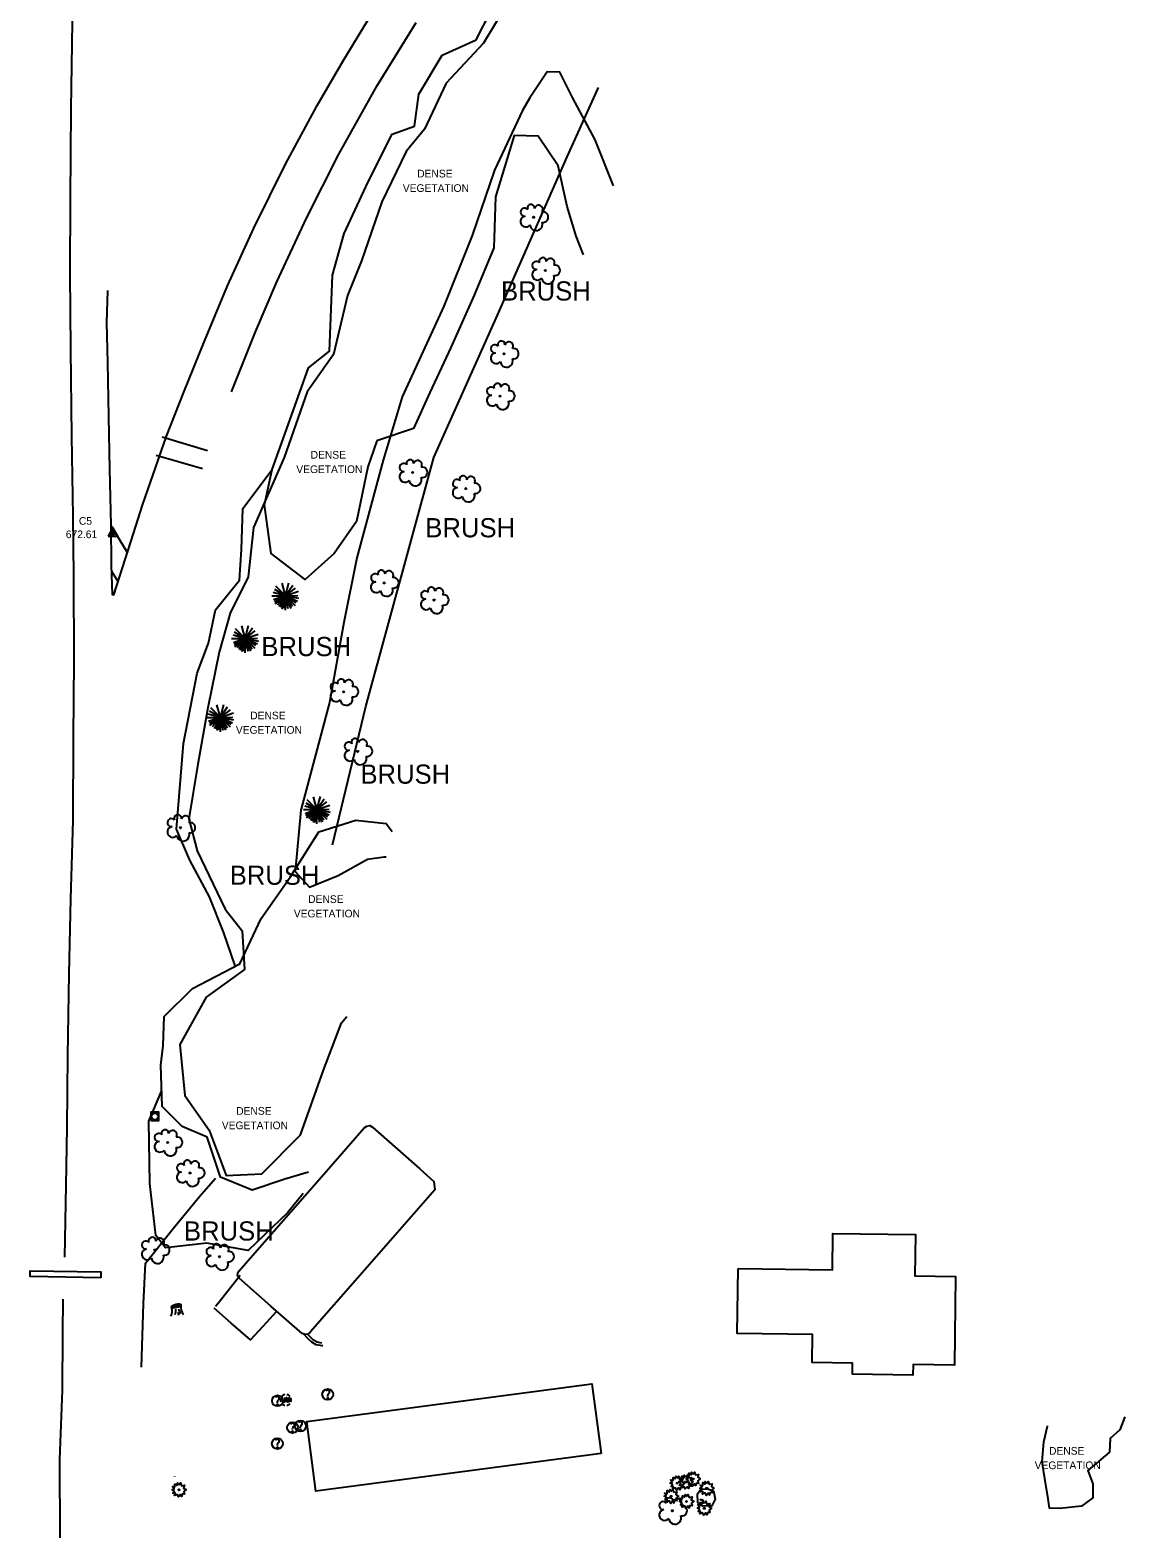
# Model space of a CAD drawing. Extents: x 2129547 to 2134906, y 657330 to 659734.
# Drawn here: x 2132485 to 2132885, y 657694 to 658244 of the extents above; entities that cross this region are included whole.
import ezdxf

# ---------------------------------------------------------------- set-up
doc = ezdxf.new("R2010")
doc.units = 0
for name, color, linetype in [('BD_X_Building', 7, 'Continuous'), ('PM_X_Crosswalk', 7, 'Continuous'), ('PM_X_Edge_Line', 7, 'Continuous'), ('PM_X_Lane_Line', 7, 'Continuous'), ('PM_X_Stop_Line', 7, 'Continuous'), ('PM_X_Transverse_Line', 7, 'Continuous'), ('PV_X_Parking_Lot', 7, 'Continuous'), ('RD_X_Cells', 7, 'Continuous'), ('RD_X_Concrete_Pad', 7, 'Continuous'), ('RD_X_Fence', 7, 'Continuous'), ('RD_X_GR_Rt', 7, 'Continuous'), ('RD_X_Misc_Items', 7, 'Continuous'), ('RD_X_Wall', 7, 'Continuous'), ('SG_X_Poles', 7, 'Continuous'), ('SV_P_Aerial_Targets', 7, 'Continuous'), ('UT_X_Misc_Cells', 7, 'Continuous'), ('UT_X_Unknown_Cells', 7, 'Continuous'), ('VG_X_Cells', 7, 'Continuous'), ('VG_X_Shrub_Line_Lt', 7, 'Continuous'), ('VG_X_Text', 7, 'Continuous'), ('VG_X_Tree_Line_Lt', 7, 'Continuous')]:
    doc.layers.add(name, color=color, linetype=linetype)

# ---------------------------------------------------------------- blocks, each defined once
blk = doc.blocks.new('DM')
at = {"layer": 'UT_X_Misc_Cells'}
blk.add_circle((0, 0), 0.00254, dxfattribs=at)
blk.add_arc((0.01016, 0), 0.01016, 90, 270, dxfattribs=at)
blk = doc.blocks.new('FCTRL')
at = {"layer": 'SV_P_Aerial_Targets'}
blk.add_lwpolyline([(-0.0229, -0.0147), (0.0229, -0.0147), (0, 0.0262)], close=True, dxfattribs=at)
for radius in [0.00889, 0.00203]:
    blk.add_circle((0, 0), radius, dxfattribs=at)
blk = doc.blocks.new('SHRUB')
at = {"layer": 'VG_X_Cells'}
blk.add_lwpolyline([(-0.0011, 0.023), (0.0066, 0.0323), (0.0119, 0.0189), (0.0257, 0.0212), (0.0214, 0.0084), (0.0334, 0.0008), (0.0226, -0.0085), (0.0257, -0.0201), (0.0162, -0.0192), (0.012, -0.0308), (0.0066, -0.0221), (-0.002, -0.0324), (-0.0075, -0.0212), (-0.0204, -0.0266), (-0.018, -0.0147), (-0.0283, -0.0157), (-0.0223, -0.0057), (-0.032, 0.0015), (-0.0226, 0.0049), (-0.0304, 0.0151), (-0.0185, 0.0137), (-0.0189, 0.0269), (-0.0093, 0.0196), (-0.0067, 0.0322), (-0.0011, 0.023)], dxfattribs=at)
blk.add_circle((0, 0), 0.00293, dxfattribs=at)
blk = doc.blocks.new('TREE')
at = {"layer": 'VG_X_Cells'}
blk.add_circle((0, 0), 0.00305, dxfattribs=at)
for centre, radius, start, end in [((-0.0362, -0.0197), 0.0251, 96.17219, 320.57371), ((-0.042, 0.0237), 0.0187, 39.06254, 279.54124), ((-0.0125, 0.0428), 0.0167, 354.0047, 205.97412), ((0.0232, 0.0359), 0.0197, 323.82996, 165.0376), ((0.0439, 0.0005), 0.0243, 259.14531, 101.45961), ((0.012, -0.0331), 0.029, 184.94757, 19.45715)]:
    blk.add_arc(centre, radius, start, end, dxfattribs=at)
blk = doc.blocks.new('UMH')
at = {"layer": 'UT_X_Unknown_Cells'}
for p, q in [((-0.017, 0.0104), (-0.017, -0.0059)), ((-0.0042, 0.0104), (-0.0042, -0.0059))]:
    blk.add_line(p, q, dxfattribs=at)
blk.add_lwpolyline([(0.0024, -0.01), (0.0024, 0.0104), (0.0099, -0.01), (0.0174, 0.0104), (0.0174, -0.01)], dxfattribs=at)
for centre, radius, start, end in [((0, 0), 0.0254, 160.01689, 200.03919), ((0, 0), 0.0254, 100.0806, 140.07213), ((0, 0), 0.0254, 40.05767, 80.10608), ((0, 0), 0.0254, 340.01689, 20.03919), ((0, 0), 0.0254, 220.05767, 260.04731), ((-0.0106, -0.0029), 0.00708, 205.19243, 334.80757), ((0, 0), 0.0254, 280.01144, 320.02638)]:
    blk.add_arc(centre, radius, start, end, dxfattribs=at)
blk = doc.blocks.new('UOBJ')
at = {"layer": 'RD_X_Misc_Items'}
blk.add_line((0, -0.0096), (0, -0.0036), dxfattribs=at)
for centre, radius in [((0, 0), 0.0254), ((0, -0.0179), 0.00216)]:
    blk.add_circle(centre, radius, dxfattribs=at)
for centre, radius, start, end in [((-0.0008, 0.0103), 0.00957, 88.32401, 152.53853), ((-0.0002, 0.0111), 0.00873, 291.93294, 92.45835), ((0.0074, -0.003), 0.00746, 125.46179, 184.08291)]:
    blk.add_arc(centre, radius, start, end, dxfattribs=at)
blk = doc.blocks.new('ETREE')
at = {"layer": 'VG_X_Cells'}
for p, q in [((-0.0627, 0), (0, 0)), ((0, 0), (-0.056, 0.015)), ((0, 0), (-0.0545, -0.0198)), ((0, 0), (-0.0506, -0.029)), ((0, 0), (-0.0496, 0.0292)), ((0, 0), (-0.0496, -0.038)), ((0, 0), (-0.0443, 0.0443)), ((0, 0), (-0.0374, -0.044)), ((0, 0), (-0.0294, -0.051)), ((0, 0), (-0.0211, -0.0551)), ((0, 0), (-0.016, -0.0617)), ((0, 0), (-0.0157, 0.0586)), ((0, 0), (-0.0069, -0.0583)), ((0, 0), (0.016, 0.0597)), ((0, 0), (0.0337, 0.0493)), ((0, 0), (0.0464, 0.0356)), ((0, 0), (0.0602, 0.0204)), ((0, 0), (0.0573, 0.0012)), ((0, -0.0665), (0, 0)), ((0, 0), (0.0117, -0.0589)), ((0, 0), (0.0246, -0.0593)), ((0, 0), (0.0322, -0.0482)), ((0, 0), (0.0456, -0.0447)), ((0, 0), (0.0485, -0.0324)), ((0, 0), (0.0567, -0.0247)), ((0, 0), (0.0613, -0.0122))]:
    blk.add_line(p, q, dxfattribs=at)
blk = doc.blocks.new('ROCK')
at = {"layer": 'RD_X_Cells'}
blk.add_lwpolyline([(-0.0388, -0.0245), (-0.0398, 0.0174), (-0.0239, 0.0387), (0.006, 0.0402), (0.0339, 0.032), (0.0415, -0.0068), (0.0272, -0.0382), (-0.0144, -0.0398), (-0.0388, -0.0245)], dxfattribs=at)
blk = doc.blocks.new('STUMP')
at = {"layer": 'VG_X_Cells'}
for centre, radius, start, end in [((-0.0741, -0.0044), 0.0508, 331.53375, 20.92689), ((-0.0701, 0.0003), 0.0642, 340.79377, 3.54808), ((0.0826, 0.0261), 0.0803, 194.9653, 212.12159), ((0.0712, 0.0145), 0.0545, 171.41061, 219.91939), ((0.0496, -0.0102), 0.0462, 178.79264, 197.12241)]:
    blk.add_arc(centre, radius, start, end, dxfattribs=at)
for major_axis in [(0.022, 0.0048), (0.0165, 0.0036), (0.0124, 0.0027), (0.00698, 0.00151), (0.00392, 0.00085)]:
    blk.add_ellipse((-0.0048, 0.0192), major_axis=major_axis, ratio=0.36865, dxfattribs=at)
blk = doc.blocks.new('SPOLE')
at = {"layer": 'SG_X_Poles'}
blk.add_lwpolyline([(-0.01905, -0.01905), (0.01905, -0.01905), (0.01905, 0.01905), (-0.01905, 0.01905)], close=True, dxfattribs=at)
blk.add_circle((0, 0), 0.01524, dxfattribs=at)

msp = doc.modelspace()

# ---------------------------------------------------------------- linework, layer by layer
at = {"layer": 'BD_X_Building'}
for points in [[(2132566.37, 657796.8), (2132591.53, 657825.54), (2132607.14, 657843.43), (2132608.06, 657844.03), (2132609.17, 657844.17), (2132610.2, 657843.58), (2132627.4, 657828.41), (2132632.58, 657823.75), (2132632.85, 657820.7), (2132611.55, 657796.46), (2132587.38, 657768.75), (2132586.55, 657768.11), (2132585.55, 657767.89), (2132584.49, 657768.33), (2132573.03, 657778.34), (2132561.41, 657788.56), (2132560.9, 657789.31), (2132560.96, 657790.3), (2132561.47, 657791.2)], [(2132743.64, 657792.02), (2132778.06, 657791.56), (2132778.24, 657804.79), (2132808.34, 657804.39), (2132808.14, 657789.33), (2132823, 657789.13), (2132822.56, 657756.77), (2132807.46, 657756.97), (2132807.41, 657753.12), (2132785.33, 657753.41), (2132785.38, 657757.54), (2132770.65, 657757.73), (2132770.78, 657767.98), (2132743.32, 657768.35)], [(2132693.59, 657724.49), (2132589.51, 657710.76), (2132586.15, 657736.19), (2132690.23, 657749.92)]]:
    msp.add_lwpolyline(points, close=True, dxfattribs=at)
at = {"layer": 'PM_X_Crosswalk'}
for p, q in [((2132533.38, 658095.53), (2132549.9, 658090.58)), ((2132531.19, 658088.83), (2132548.06, 658084.06))]:
    msp.add_line(p, q, dxfattribs=at)
at = {"layer": 'PM_X_Edge_Line'}
for points in [[(2132513.43, 658149.03), (2132513.02, 658137.15), (2132513.36, 658122.7), (2132513.73, 658103.01), (2132514.1, 658083.8), (2132514.56, 658063.33), (2132514.79, 658048.73), (2132515.1, 658037.98), (2132515.74, 658037.91), (2132521.92, 658057.2), (2132526.28, 658071), (2132531.94, 658087.08), (2132532.43, 658088.48), (2132534.7, 658095.13), (2132534.95, 658095.87), (2132541.21, 658111.84), (2132548.77, 658130.52), (2132557.27, 658150.66), (2132566.78, 658171.72), (2132578.4, 658195.13), (2132589.95, 658216.51), (2132599.45, 658232.83), (2132612.14, 658253.6)], [(2132558.65, 658112.05), (2132567.39, 658133.93), (2132575.27, 658152.17), (2132586.01, 658175.38), (2132597.91, 658198.69), (2132611.72, 658223.57), (2132626.05, 658246.77)]]:
    msp.add_lwpolyline(points, dxfattribs=at)
at = {"layer": 'PM_X_Lane_Line'}
for points in [[(2132503.6, 658398.19), (2132503.09, 658377.47), (2132502.58, 658352.54), (2132501.97, 658326.21), (2132501.38, 658295.33), (2132500.9, 658272.06), (2132500.5, 658246.92), (2132500.04, 658215.33), (2132499.74, 658182.46), (2132499.63, 658155.29), (2132499.86, 658127.46), (2132500.32, 658095.82), (2132500.8, 658066.58), (2132501.04, 658044.97), (2132501.15, 658013.81), (2132500.9, 657985.86), (2132500.74, 657955.54), (2132499.92, 657926.93), (2132499.27, 657899.62), (2132498.78, 657869.82), (2132498.51, 657843.52), (2132498.18, 657822.42), (2132497.65, 657796.23)], [(2132496.09, 657693.73), (2132496.04, 657722.34), (2132496.92, 657747.65), (2132497.13, 657768.39), (2132497.24, 657780.9)]]:
    msp.add_lwpolyline(points, dxfattribs=at)
at = {"layer": 'PM_X_Stop_Line'}
msp.add_lwpolyline([(2132510.96, 657788.65), (2132485.16, 657789.08), (2132485.2, 657791.19), (2132511, 657790.76)], close=True, dxfattribs=at)
at = {"layer": 'PM_X_Transverse_Line'}
for p, q in [((2132514.56, 658063.22), (2132520.66, 658053.26)), ((2132514.85, 658046.51), (2132517.24, 658042.61))]:
    msp.add_line(p, q, dxfattribs=at)
at = {"layer": 'PV_X_Parking_Lot'}
msp.add_lwpolyline([(2132561.8, 657789.43), (2132553.7, 657779.18), (2132552.84, 657778.13)], dxfattribs=at)
at = {"layer": 'RD_X_Concrete_Pad'}
msp.add_lwpolyline([(2132575.13, 657776.5), (2132574.93, 657776.27), (2132571.4, 657772.27), (2132565.56, 657766.01), (2132558.59, 657772.06), (2132552.35, 657777.52)], dxfattribs=at)
at = {"layer": 'RD_X_Fence'}
for p, q in [((2132681.16, 658197.76), (2132692.59, 658223.04)), ((2132525.78, 657756), (2132526.53, 657779.13))]:
    msp.add_line(p, q, dxfattribs=at)
for points in [[(2132595.52, 657946.7), (2132607.69, 657997.15), (2132632.53, 658088.02), (2132655.83, 658139.95), (2132681.16, 658197.76)], [(2132526.53, 657779.13), (2132527.31, 657793.98), (2132537.39, 657806.6), (2132547.01, 657818.36), (2132552.82, 657825.04)]]:
    msp.add_lwpolyline(points, dxfattribs=at)
at = {"layer": 'RD_X_GR_Rt'}
msp.add_line((2132537.9, 657716.09), (2132537.86, 657716), dxfattribs=at)
at = {"layer": 'RD_X_Misc_Items'}
for points in [[(2132659.14, 658253.41), (2132650.69, 658239.25), (2132637.08, 658224.71), (2132629.09, 658207.83), (2132622.38, 658199.73), (2132613.51, 658181.37), (2132606.16, 658159.76), (2132601.06, 658147.17), (2132595.86, 658125.65), (2132586.24, 658112.01), (2132577.91, 658087.97), (2132566.64, 658062.51), (2132564.77, 658044.46), (2132558.16, 658031.16), (2132554.15, 658017.04), (2132550.04, 657996.61), (2132546.4, 657976.07), (2132543.06, 657956.16), (2132546.16, 657944.53), (2132556.31, 657923.18), (2132562.52, 657915.27), (2132563.43, 657901.11), (2132549.43, 657891.03), (2132539.83, 657873.74), (2132541.62, 657855.16), (2132550.46, 657842.48), (2132556.7, 657826), (2132569.71, 657826.54), (2132583.86, 657840.77), (2132592.29, 657864.37), (2132598.81, 657881.67), (2132600.74, 657883.96)], [(2132698.09, 658187.13), (2132691.37, 658203.91), (2132683.17, 658219.48), (2132678.54, 658228.64), (2132673.94, 658228.75), (2132667.58, 658219.31), (2132664.85, 658214.73), (2132654.71, 658192.86), (2132646.57, 658169), (2132636.16, 658143.29), (2132620.92, 658110.19), (2132614.07, 658087.11), (2132604.39, 658051.44), (2132599.62, 658027.75), (2132594.39, 657998.62), (2132584.03, 657959.36), (2132581.91, 657936.92), (2132587.14, 657931.19), (2132597.57, 657935.46), (2132608.36, 657941.42), (2132614.41, 657942.28), (2132615.08, 657942.23)]]:
    msp.add_lwpolyline(points, dxfattribs=at)
at = {"layer": 'RD_X_Wall'}
for points in [[(2132591.98, 657763.81), (2132591.77, 657763.8), (2132589.58, 657764.14), (2132588.02, 657765.12), (2132586.53, 657766.5), (2132584.95, 657768.14)], [(2132591.62, 657764.83), (2132589.93, 657765.1), (2132588.63, 657765.91), (2132587.24, 657767.21), (2132586.4, 657768.08)]]:
    msp.add_lwpolyline(points, dxfattribs=at)
at = {"layer": 'VG_X_Shrub_Line_Lt'}
for points in [[(2132559.97, 657902.52), (2132555.86, 657914.51), (2132550.66, 657927.67), (2132543.46, 657941.1), (2132538.62, 657952.41), (2132541.13, 657983.61), (2132546.16, 658009.36), (2132550.3, 658020.32), (2132552.86, 658032.42), (2132561.57, 658043.3), (2132562.33, 658054.5), (2132562.84, 658069.38), (2132573.5, 658083.71)], [(2132584.83, 657819.35), (2132579.13, 657812.35), (2132564.74, 657798.63), (2132549.69, 657801.28), (2132534.55, 657799.56), (2132531.01, 657804.02), (2132528.86, 657823.05), (2132528.51, 657845.77), (2132533.2, 657857.01)]]:
    msp.add_lwpolyline(points, dxfattribs=at)
at = {"layer": 'VG_X_Tree_Line_Lt'}
for points in [[(2132687.11, 658161.98), (2132684.49, 658168.79), (2132681.26, 658179.59), (2132677.91, 658194.47), (2132670.58, 658205.26), (2132661.85, 658205.53), (2132655.04, 658183.14), (2132654.45, 658164.51), (2132647.24, 658147.32), (2132638.69, 658128.15), (2132631.07, 658111.79), (2132625.16, 658098.6), (2132611.7, 658094.14), (2132608.46, 658084.65), (2132604.27, 658064.67), (2132596.2, 658053.03), (2132585.56, 658043.45), (2132573.2, 658052.98), (2132570.7, 658070.77), (2132573.5, 658083.71), (2132578.12, 658096.54), (2132586.82, 658120.78), (2132594.44, 658126.83), (2132595.53, 658154.62), (2132599.76, 658169.78), (2132608.52, 658188.7), (2132617.31, 658206.09), (2132625.52, 658208.98), (2132627.06, 658220.69), (2132635.63, 658234.88), (2132647.98, 658240.45), (2132658.44, 658261.04)], [(2132586.75, 657827.16), (2132578.2, 657824.66), (2132566.21, 657820.68), (2132554.62, 657825.34), (2132549.73, 657840), (2132540.67, 657843.82), (2132533.39, 657851.12), (2132532.89, 657866.24), (2132533.75, 657873.48), (2132534.11, 657883.97), (2132544.49, 657894.27), (2132561.71, 657903.17), (2132569.44, 657919.75), (2132580.08, 657934.83), (2132590.61, 657951.42), (2132604.06, 657955.65), (2132615.09, 657954.5), (2132617.36, 657951.48)], [(2132884.8, 657737.84), (2132882.96, 657733.21), (2132879.48, 657729.95), (2132879.21, 657725.06), (2132871.3, 657718.35), (2132873.1, 657713.49), (2132873.09, 657708.33), (2132868.95, 657705.34), (2132861.02, 657704.41), (2132857.29, 657704.53), (2132856.82, 657708), (2132855.59, 657715.4), (2132854.6, 657721.45), (2132855.17, 657728.72), (2132856.6, 657734.48), (2132856.61, 657734.57)]]:
    msp.add_lwpolyline(points, dxfattribs=at)

# ---------------------------------------------------------------- block references
at = {"layer": 'RD_X_Cells', "xscale": 78.74000000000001, "yscale": 78.74000000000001}
msp.add_blockref('ROCK', (2132731.92, 657708.42), dxfattribs=at)
at = {"layer": 'RD_X_Misc_Items', "xscale": 78.74000000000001, "yscale": 78.74000000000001}
for p in [(2132575.46, 657743.75), (2132593.82, 657746.09), (2132580.97, 657733.98), (2132583.85, 657734.54), (2132575.44, 657728.13)]:
    msp.add_blockref('UOBJ', p, dxfattribs=at)
at = {"layer": 'SG_X_Poles', "xscale": 78.74000000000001, "yscale": 78.74000000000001}
msp.add_blockref('SPOLE', (2132530.69, 657847.55), dxfattribs=at)
at = {"layer": 'SV_P_Aerial_Targets', "xscale": 78.74000000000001, "yscale": 78.74000000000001}
msp.add_blockref('FCTRL', (2132515.39, 658060.46), dxfattribs=at)
at = {"layer": 'UT_X_Misc_Cells', "xscale": 78.74000000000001, "yscale": 78.74000000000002, "rotation": -143.04393387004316}
msp.add_blockref('DM', (2132730.77, 657707.34), dxfattribs=at)
at = {"layer": 'UT_X_Unknown_Cells', "xscale": 78.74000000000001, "yscale": 78.74000000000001}
msp.add_blockref('UMH', (2132578.5, 657744.08), dxfattribs=at)
at = {"layer": 'VG_X_Cells', "xscale": 78.74000000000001, "yscale": 78.74000000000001}
for name, p in [('TREE', (2132668.96, 658175.71)), ('TREE', (2132673.25, 658156.29)), ('TREE', (2132658.13, 658125.86)), ('TREE', (2132656.72, 658110.42)), ('TREE', (2132624.82, 658082.56)), ('TREE', (2132644.22, 658076.7)), ('TREE', (2132614.39, 658042.26)), ('ETREE', (2132578.35, 658037.59)), ('TREE', (2132632.64, 658035.99)), ('ETREE', (2132563.65, 658021.97)), ('TREE', (2132599.65, 658002.5)), ('ETREE', (2132554.6, 657993.19)), ('TREE', (2132604.76, 657980.77)), ('ETREE', (2132589.84, 657959.56)), ('TREE', (2132540.06, 657952.9)), ('TREE', (2132535.38, 657838.03)), ('TREE', (2132543.54, 657826.89)), ('TREE', (2132530.71, 657798.74)), ('TREE', (2132554.28, 657796.34)), ('STUMP', (2132538.87, 657776.88)), ('SHRUB', (2132724.5, 657714.12)), ('SHRUB', (2132727.17, 657715.2)), ('SHRUB', (2132539.5, 657711.26)), ('SHRUB', (2132719.17, 657708.87)), ('SHRUB', (2132721.37, 657713.68)), ('SHRUB', (2132732.17, 657711.79)), ('TREE', (2132719.6, 657703.62)), ('SHRUB', (2132724.77, 657707)), ('SHRUB', (2132731.25, 657704.54))]:
    msp.add_blockref(name, p, dxfattribs=at)

# ---------------------------------------------------------------- texts
at = {"layer": 'SV_P_Aerial_Targets'}
for s, p in [('C5', (2132502.96, 658063.49)), ('672.61', (2132498.19, 658058.59))]:
    msp.add_text(s, height=2.8, dxfattribs=at).set_placement(p)
at = {"layer": 'VG_X_Text'}
for s, height, p in [('DENSE', 2.8, (2132626.46, 658190.24)), ('VEGETATION', 2.8, (2132621.22, 658184.96)), ('BRUSH', 7, (2132657.07, 658145.31)), ('DENSE', 2.8, (2132587.56, 658087.62)), ('VEGETATION', 2.8, (2132582.32, 658082.35)), ('BRUSH', 7, (2132629.43, 658058.9)), ('BRUSH', 7, (2132569.57, 658015.53)), ('DENSE', 2.8, (2132565.51, 657992.47)), ('VEGETATION', 2.8, (2132560.27, 657987.2)), ('BRUSH', 7, (2132605.74, 657968.97)), ('BRUSH', 7, (2132558.03, 657932.08)), ('DENSE', 2.8, (2132586.68, 657925.45)), ('VEGETATION', 2.8, (2132581.43, 657920.18)), ('DENSE', 2.8, (2132560.39, 657848.15)), ('VEGETATION', 2.8, (2132555.15, 657842.88)), ('BRUSH', 7, (2132541.32, 657802.23)), ('DENSE', 2.8, (2132857.12, 657724.08)), ('VEGETATION', 2.8, (2132851.88, 657718.81))]:
    msp.add_text(s, height=height, dxfattribs=at).set_placement(p)

doc.saveas('drawing.dxf')
